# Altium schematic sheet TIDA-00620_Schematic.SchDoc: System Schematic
size 431 x 279 mm; Date: Not shown in title block; ApprovedBy: Not shown in title block; CheckedBy: Not shown in title block; Author: Not shown in title block; CompanyName: Not shown in title block; DrawnBy: Koh Hamasaki; Engineer: Not shown in title block; Organization: Not shown in title block; Address1: Not shown in title block; Address2: Not shown in title block; Address3: Not shown in title block; Address4: Not shown in title block; DocumentNumber: 1; Revision: Use project parameter SCH_Rev; SheetNumber: 1; SheetTotal: 2; PageSetup: Record=PageOptions¦CenterHorizontal=True¦CenterVertical=True¦PrintScale=0.64¦XCorrection=1.00¦YCorrection=1.00¦PrintKind=0¦BorderSize=5000000¦LeftOffset=0¦BottomOffset=0¦Orientation=2¦PaperLength=1000¦PaperWidth=1000¦Scale=100¦PaperSource=15¦PrintQuality=600¦MediaType=1¦DitherType=10¦PrintScaleMode=1¦PaperKind=Letter
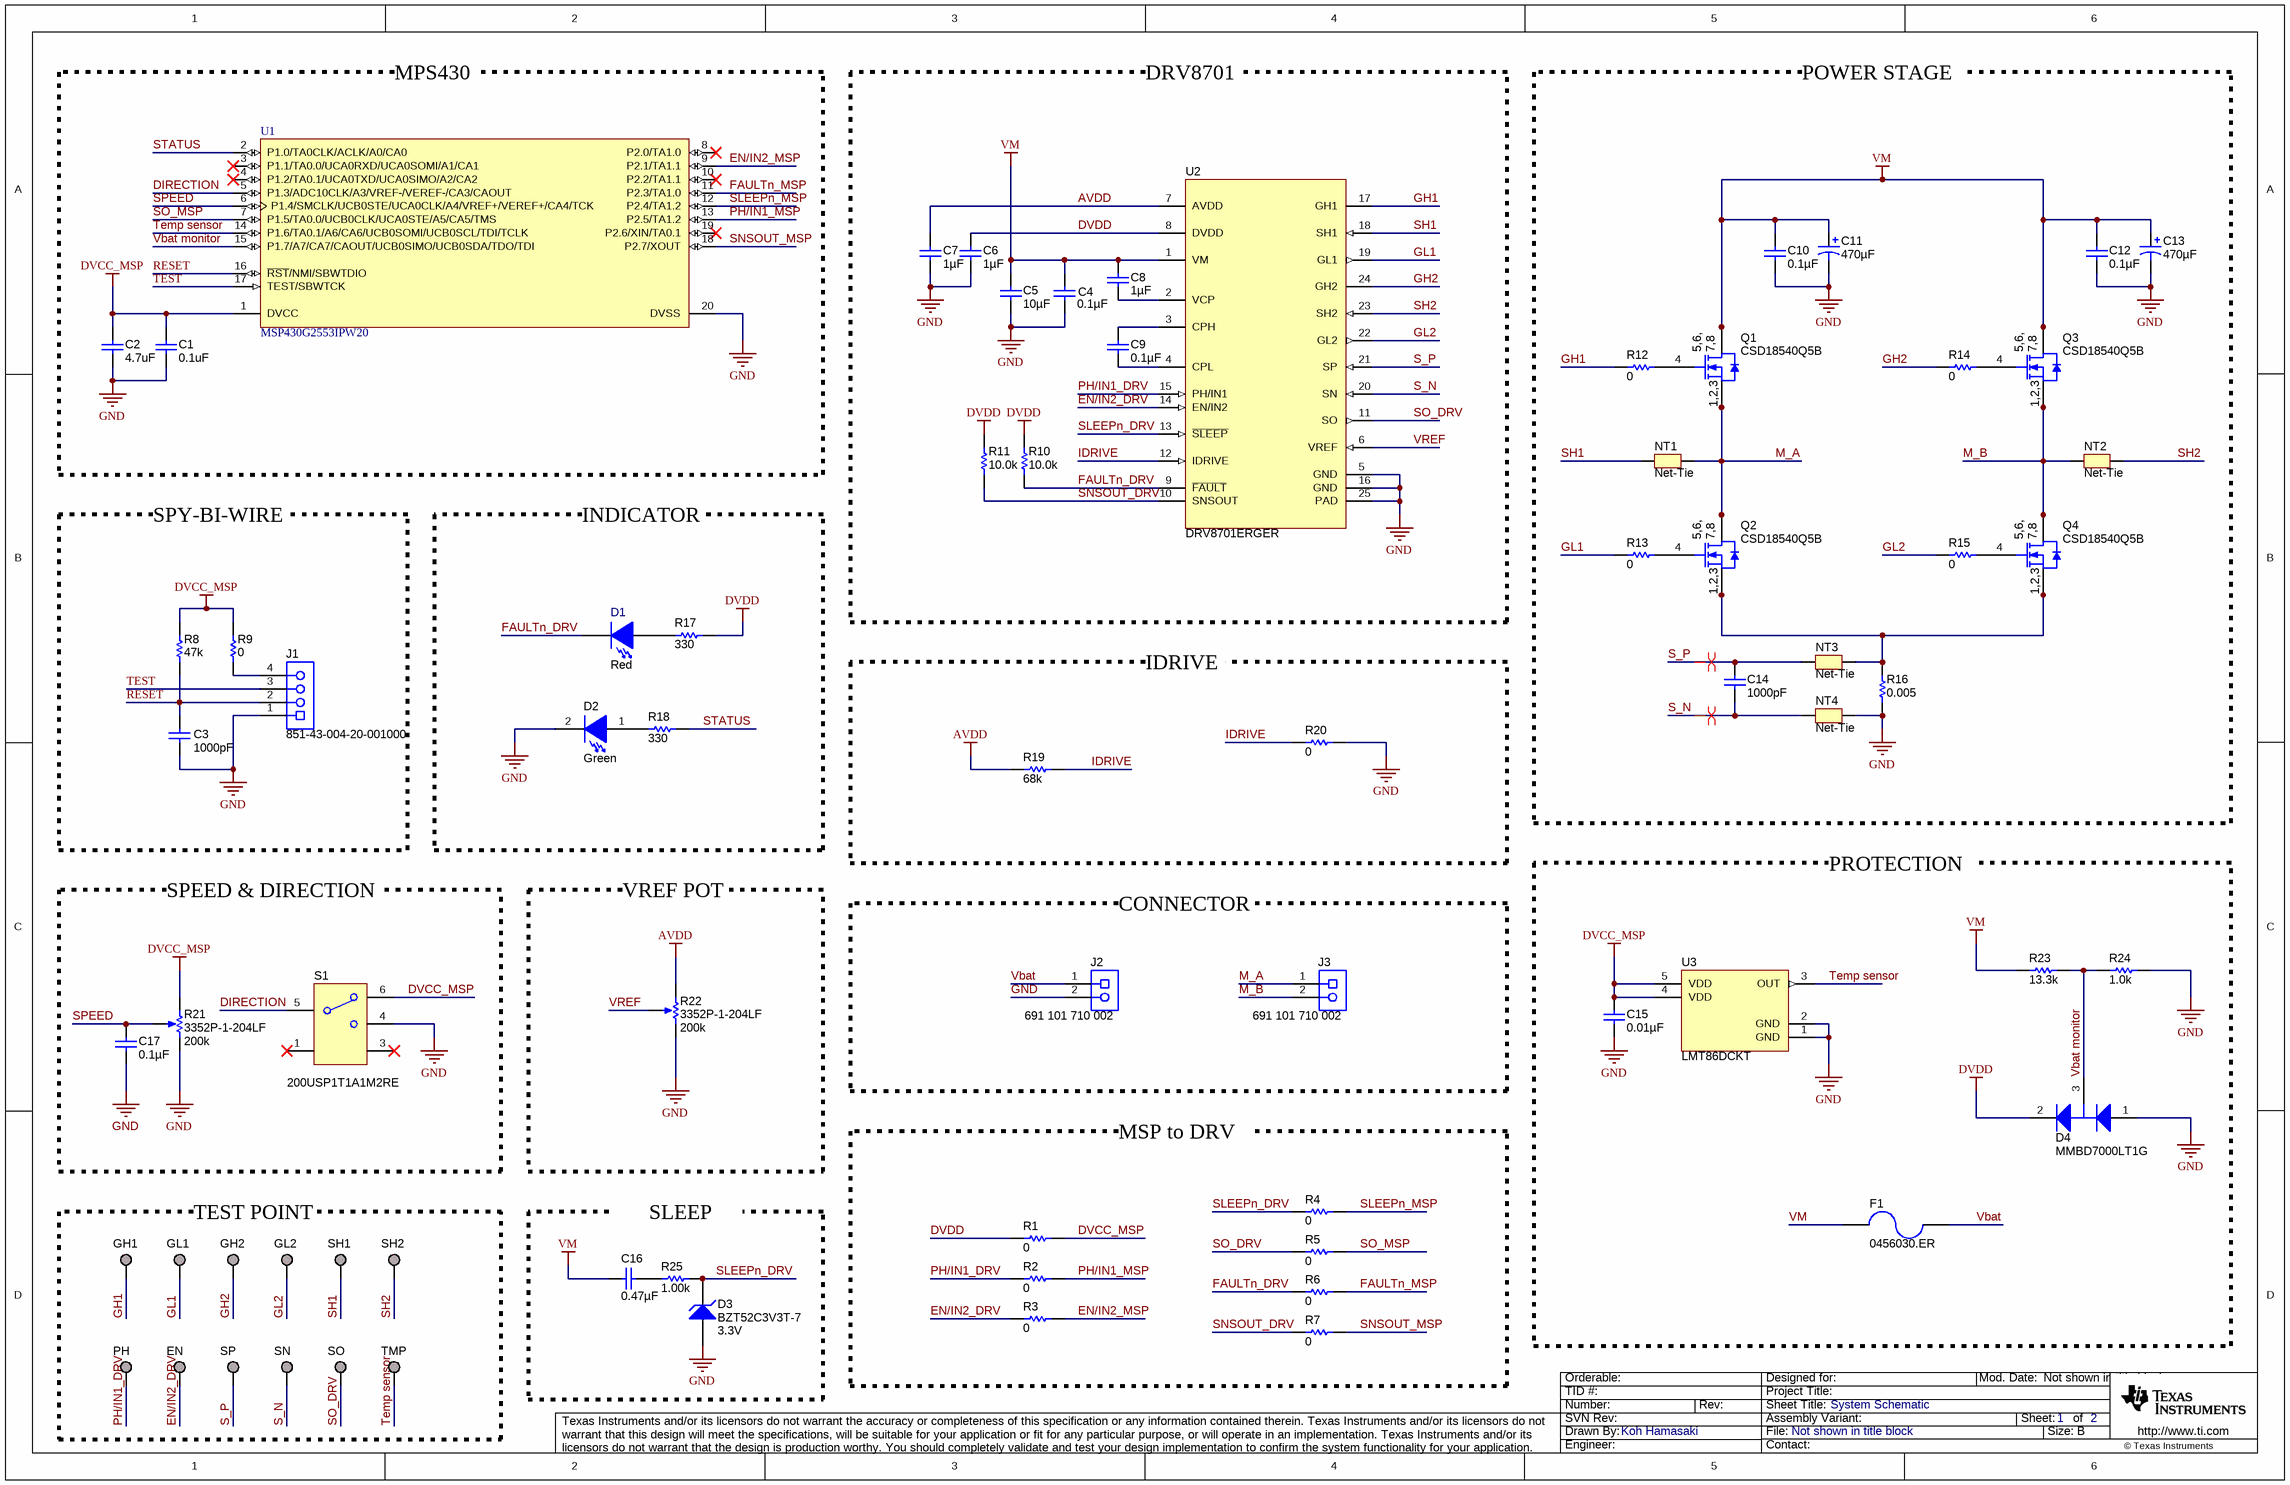
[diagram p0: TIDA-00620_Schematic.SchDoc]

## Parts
C1  ValueDisplayed: 0.1uF  [0603L]  (hidden comment: C0603C104K8RACTU)
C2  ValueDisplayed: 4.7uF  [0805L]  (hidden comment: C2012X7R1A475M)
C3  ValueDisplayed: 1000pF  [0603L]  (hidden comment: GRM188R71C102KA01D)
C4  ValueDisplayed: 0.1µF  [1206L]  (hidden comment: GRM319R71H104KA01D)
C5  ValueDisplayed: 10µF  [1210L]  (hidden comment: GRM32ER71H106KA12L)
C6  ValueDisplayed: 1µF  [0603L]  (hidden comment: GRM188R60J105KA01D)
C7  ValueDisplayed: 1µF  [0603L]  (hidden comment: GRM188R60J105KA01D)
C8  ValueDisplayed: 1µF  [1206L]  (hidden comment: GRM319R71C105KAA3D)
C9  ValueDisplayed: 0.1µF  [0402L]  (hidden comment: GRM155R71C104KA88D)
C10  ValueDisplayed: 0.1µF  [1206L]  (hidden comment: GRM319R71H104KA01D)
C11  ValueDisplayed: 470µF  [CAPPRD350W60D800H2000]  (hidden comment: EEU-FR1V471LB)
C12  ValueDisplayed: 0.1µF  [1206L]  (hidden comment: GRM319R71H104KA01D)
C13  ValueDisplayed: 470µF  [CAPPRD350W60D800H2000]  (hidden comment: EEU-FR1V471LB)
C14  ValueDisplayed: 1000pF  [0402L]  (hidden comment: GRM155R71C102KA01D)
C15  ValueDisplayed: 0.01µF  [0603L]  (hidden comment: GRM188R70J103KA01D)
C16  ValueDisplayed: 0.47µF  [0402L]  (hidden comment: GRM155R61A474KE15D)
C17  ValueDisplayed: 0.1µF  [0402]  (hidden comment: GCM155R71C104KA55D)
D1  value Red  [LED_LTST-C170]  (hidden comment: nFAULT)
D2  value Green  [LED_LTST-C171]  (hidden comment: LTST-C171GKT)
D3  BZT52C3V3T-7  value 3.3V  [SOD-523]
D4  MMBD7000LT1G  [SOT-23]
EN  TESTPOINT  [TP_25MIL-SMT]  (value not drawn)  (no BOM)
F1  0456030.ER  [FUSE_0456030]
GH1  TESTPOINT  [TP_25MIL-SMT]  (value not drawn)  (no BOM)
GH2  TESTPOINT  [TP_25MIL-SMT]  (value not drawn)  (no BOM)
GL1  TESTPOINT  [TP_25MIL-SMT]  (value not drawn)  (no BOM)
GL2  TESTPOINT  [TP_25MIL-SMT]  (value not drawn)  (no BOM)
J1  851-43-004-20-001000  [CONN_851-43-004-20-001000]
J2  691 101 710 002  [Wurth_691101710002]
J3  691 101 710 002  [Wurth_691101710002]
NT1  Net-Tie  [Net-Tie_10milWide_30milLong]  (net tie, no BOM)
NT2  Net-Tie  [Net-Tie_10milWide_30milLong]  (net tie, no BOM)
NT3  Net-Tie  [Net-Tie_10milWide_30milLong]  (net tie, no BOM)
NT4  Net-Tie  [Net-Tie_10milWide_30milLong]  (net tie, no BOM)
PH  TESTPOINT  [TP_25MIL-SMT]  (value not drawn)  (no BOM)
Q1  CSD18540Q5B  [TRANS_NexFET_Q5B]
Q2  CSD18540Q5B  [TRANS_NexFET_Q5B]
Q3  CSD18540Q5B  [TRANS_NexFET_Q5B]
Q4  CSD18540Q5B  [TRANS_NexFET_Q5B]
R1  ValueDisplayed: 0  [0402L]  (hidden comment: CRCW04020000Z0ED)
R2  ValueDisplayed: 0  [0402L]  (hidden comment: CRCW04020000Z0ED)
R3  ValueDisplayed: 0  [0402L]  (hidden comment: CRCW04020000Z0ED)
R4  ValueDisplayed: 0  [0402L]  (hidden comment: CRCW04020000Z0ED)
R5  ValueDisplayed: 0  [0402L]  (hidden comment: CRCW04020000Z0ED)
R6  ValueDisplayed: 0  [0402L]  (hidden comment: CRCW04020000Z0ED)
R7  ValueDisplayed: 0  [0402L]  (hidden comment: CRCW04020000Z0ED)
R8  value 47k  [0603L]  (hidden comment: CRCW060347K0JNEA)
R9  value 0  [0603L]  (hidden comment: CRCW06030000Z0EA)
R10  ValueDisplayed: 10.0k  [0402L]  (hidden comment: ERJ-2RKF1002X)
R11  ValueDisplayed: 10.0k  [0402L]  (hidden comment: ERJ-2RKF1002X)
R12  ValueDisplayed: 0  [0402L]  (hidden comment: CRCW04020000Z0ED)
R13  ValueDisplayed: 0  [0402L]  (hidden comment: CRCW04020000Z0ED)
R14  ValueDisplayed: 0  [0402L]  (hidden comment: CRCW04020000Z0ED)
R15  ValueDisplayed: 0  [0402L]  (hidden comment: CRCW04020000Z0ED)
R16  ValueDisplayed: 0.005  [4320]  (hidden comment: KRL11050-C-R005-F-T1)
R17  ValueDisplayed: 330  [0603L]  (hidden comment: RC0603FR-07330RL)
R18  ValueDisplayed: 330  [0603L]  (hidden comment: RC0603FR-07330RL)
R19  ValueDisplayed: 68k  [0402]  (hidden comment: CRCW040268K0JNED)
R20  ValueDisplayed: 0  [0402L]  (hidden comment: CRCW04020000Z0ED)
R21  3352P-1-204LF  value 200k  [Bourns_3352P]
R22  3352P-1-204LF  value 200k  [Bourns_3352P]
R23  ValueDisplayed: 13.3k  [0402L]  (hidden comment: CRCW040213K3FKED)
R24  ValueDisplayed: 1.0k  [0402L]  (hidden comment: CRCW04021K00JNED)
R25  ValueDisplayed: 1.00k  [0402L]  (hidden comment: CRCW04021K00FKED)
S1  200USP1T1A1M2RE  [SW_200USP1T1A1M2]
SH1  TESTPOINT  [TP_25MIL-SMT]  (value not drawn)  (no BOM)
SH2  TESTPOINT  [TP_25MIL-SMT]  (value not drawn)  (no BOM)
SN  TESTPOINT  [TP_25MIL-SMT]  (value not drawn)  (no BOM)
SO  TESTPOINT  [TP_25MIL-SMT]  (value not drawn)  (no BOM)
SP  TESTPOINT  [TP_25MIL-SMT]  (value not drawn)  (no BOM)
TMP  TESTPOINT  [TP_25MIL-SMT]  (value not drawn)  (no BOM)
U1  MSP430G2553IPW20  [PW0020A_N]
U2  DRV8701ERGER  [RGE0024F]
U3  LMT86DCKT  [DCK0005A_N]

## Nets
AVDD: C7.1 R19.1 R22.1(CCW) U2.7(AVDD)
DVCC_MSP: C1.1 C2.1 C15.1 R1.2 R8.2 R9.2 R21.1(CCW) S1.6 U1.1(DVCC) U3.4(VDD) U3.5(VDD)
DVDD: C6.1 D4.2(K) R1.1 R10.2 R11.2 R17.2 U2.8(DVDD)
GND: C1.2 C2.2 C3.2 C4.2 C5.2 C6.2 C7.2 C10.2 C11.2(-) C12.2 C13.2(-) C15.2 C17.2 D2.2(K) D3.2(A) D4.1(A) J1.1 J2.2 NT4.2 R16.1 R20.2 R21.3(CW) R22.3(CW) R24.2 S1.4 U1.20(DVSS) U2.5(GND) U2.16(GND) U2.25(PAD) U3.1(GND) U3.2(GND)
VM: C4.1 C5.1 C8.1 C10.1 C11.1(+) C12.1 C13.1(+) C16.2 F1.2 Q1.5(D) Q1.6(D) Q1.7(D) Q1.8(D) Q3.5(D) Q3.6(D) Q3.7(D) Q3.8(D) R23.1 U2.1(VM)
DIRECTION: S1.5(COM) U1.5(P1.3/ADC10CLK/A3/VREF-/VEREF-/CA3/CAOUT)
EN/IN2_DRV: EN.1 R3.1 U2.14(EN/IN2)
EN/IN2_MSP: R3.2 U1.9(P2.1/TA1.1)
FAULTn_DRV: D1.2(K) R6.1 R10.1 U2.9(~{FAULT})
FAULTn_MSP: R6.2 U1.11(P2.3/TA1.0)
GH1: GH1.1 R12.1 U2.17(GH1)
GH2: GH2.1 R14.1 U2.24(GH2)
GL1: GL1.1 R13.1 U2.19(GL1)
GL2: GL2.1 R15.1 U2.22(GL2)
IDRIVE: R19.2 R20.1 U2.12(IDRIVE)
M_A: J3.1 NT1.2 Q1.1(S) Q1.2(S) Q1.3(S) Q2.5(D) Q2.6(D) Q2.7(D) Q2.8(D)
M_B: J3.2 NT2.1 Q3.1(S) Q3.2(S) Q3.3(S) Q4.5(D) Q4.6(D) Q4.7(D) Q4.8(D)
PH/IN1_DRV: PH.1 R2.1 U2.15(PH/IN1)
PH/IN1_MSP: R2.2 U1.13(P2.5/TA1.2)
RESET: C3.1 J1.2 R8.1 U1.16(~{RST}/NMI/SBWTDIO)
S_N: C14.2 NT4.1 SN.1 U2.20(SN)
S_P: C14.1 NT3.1 SP.1 U2.21(SP)
SH1: NT1.1 SH1.1 U2.18(SH1)
SH2: NT2.2 SH2.1 U2.23(SH2)
SLEEPn_DRV: D3.1(K) R4.1 R25.2 U2.13(~{SLEEP})
SLEEPn_MSP: R4.2 U1.12(P2.4/TA1.2)
SNSOUT_DRV: R7.1 R11.1 U2.10(SNSOUT)
SNSOUT_MSP: R7.2 U1.18(P2.7/XOUT)
SO_DRV: R5.1 SO.1 U2.11(SO)
SO_MSP: R5.2 U1.7(P1.5/TA0.0/UCB0CLK/UCA0STE/A5/CA5/TMS)
SPEED: C17.1 R21.2(WIPER) U1.6(P1.4/SMCLK/UCB0STE/UCA0CLK/A4/VREF+/VEREF+/CA4/TCK)
STATUS: R18.2 U1.2(P1.0/TA0CLK/ACLK/A0/CA0)
Temp sensor: TMP.1 U1.14(P1.6/TA0.1/A6/CA6/UCB0SOMI/UCB0SCL/TDI/TCLK) U3.3(OUT)
TEST: J1.3 U1.17(TEST/SBWTCK)
Vbat: F1.1 J2.1
Vbat monitor: D4.3(C) R23.2 R24.1 U1.15(P1.7/A7/CA7/CAOUT/UCB0SIMO/UCB0SDA/TDO/TDI)
VREF: R22.2(WIPER) U2.6(VREF)
NetC8_2: C8.2 U2.2(VCP)
NetC9_1: C9.1 U2.3(CPH)
NetC9_2: C9.2 U2.4(CPL)
NetC16_1: C16.1 R25.1
NetD1_1: D1.1(A) R17.1
NetD2_1: D2.1(A) R18.1
NetJ1_4: J1.4 R9.1
NetNT3_2: NT3.2 Q2.1(S) Q2.2(S) Q2.3(S) Q4.1(S) Q4.2(S) Q4.3(S) R16.2
NetQ1_4: Q1.4(G) R12.2
NetQ2_4: Q2.4(G) R13.2
NetQ3_4: Q3.4(G) R14.2
NetQ4_4: Q4.4(G) R15.2

Not connected (* = marked no-connect by the designer): S1 1* 3*; U1 3(P1.1/TA0.0/UCA0RXD/UCA0SOMI/A1/CA1)* 4(P1.2/TA0.1/UCA0TXD/UCA0SIMO/A2/CA2)* 8(P2.0/TA1.0)* 10(P2.2/TA1.1)* 19(P2.6/XIN/TA0.1)*

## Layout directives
differential pair: S_N, S_P

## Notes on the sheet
- MPS430
- DRV8701
- POWER STAGE
- SPY-BI-WIRE
- INDICATOR
- IDRIVE
- SPEED & DIRECTION
- VREF POT
- PROTECTION
- CONNECTOR
- MSP to DRV
- TEST POINT
- SLEEP

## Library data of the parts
C1 = C0603C104K8RACTU: CAP, CERM, 0.1uF, 10V, +/-10%, X7R, 0603; Manufacturer: Kemet; Polarized: N; CompType: Capacitor; U/M: EA; Cap_F: 0.0000001; Tolerance_%: 10; Value1: Unknown; TaMin_C: -55; TaMax_C: 125; Cap_Case: 0603
C2 = C2012X7R1A475M: CAP, CERM, 4.7uF, 10V, +/-20%, X7R, 0805; Manufacturer: TDK; Polarized: N; CompType: Capacitor; U/M: EA; Cap_F: 0.0000047; Tolerance_%: 20; Value1: Unknown; VDC_V: 10; TaMin_C: -55; TaMax_C: 125; Cap_Case: 0805
C3 = GRM188R71C102KA01D: CAP, CERM, 1000pF, 16V, +/-10%, X7R, 0603; Manufacturer: MuRata; Polarized: N; CompType: Capacitor; U/M: EA; Cap_F: 0.000000001; Tolerance_%: 10; Value1: Unknown; VDC_V: 16; TaMin_C: -55; TaMax_C: 125; Cap_Case: 0603
C4 C10 C12 = GRM319R71H104KA01D: CAP, CERM, 0.1 µF, 50 V, +/- 10%, X7R, 1206; Manufacturer: MuRata; Polarized: N; CompType: Capacitor; Value: 0.1uF; U/M: EA; Cap_F: 0.0000001; Tolerance_%: 10; ESR_ohm: 0.01; Value1: 0.01 ohm; VDC_V: 50; Value2: 50V; IRMS_A: 0.9; TaMin_C: -55; TaMax_C: 125; Cap_Case: 1206
C5 = GRM32ER71H106KA12L: CAP, CERM, 10 µF, 50 V, +/- 10%, X7R, 1210; Manufacturer: MuRata; Polarized: N; CompType: Capacitor; Value: 10uF; U/M: EA; Cap_F: 0.00001; Tolerance_%: 10; Value1: Unknown; VDC_V: 50; Value2: 50V; TaMin_C: -55; TaMax_C: 125; Cap_Case: 1210
C6 C7 = GRM188R60J105KA01D: CAP, CERM, 1 µF, 6.3 V, +/- 10%, X5R, 0603; Manufacturer: MuRata; Polarized: N; CompType: Capacitor; Value: 1uF; U/M: EA; Cap_F: 0.000001; Tolerance_%: 10; Value1: Unknown; VDC_V: 6.3; Value2: 6.3V; TaMin_C: -55; TaMax_C: 85; Cap_Case: 0603
C8 = GRM319R71C105KAA3D: CAP, CERM, 1 µF, 16 V, +/- 10%, X7R, 1206; Manufacturer: MuRata; Polarized: N; CompType: Capacitor; Value: 1uF; U/M: EA; Cap_F: 0.000001; Tolerance_%: 10; Value1: Unknown; VDC_V: 16; Value2: 16V; TaMin_C: -55; TaMax_C: 125; Cap_Case: 1206
C9 = GRM155R71C104KA88D: CAP, CERM, 0.1 µF, 16 V, +/- 10%, X7R, 0402; Manufacturer: MuRata; Polarized: N; CompType: Capacitor; Value: 0.1uF; U/M: EA; Cap_F: 0.0000001; Tolerance_%: 10; Value1: Unknown; VDC_V: 16; Value2: 16V; TaMin_C: -55; TaMax_C: 125; Cap_Case: 0402
C11 C13 = EEU-FR1V471LB: CAP, AL, 470 µF, 35 V, +/- 20%, 0.03 ohm, TH; Manufacturer: Panasonic; Polarized: Y; CompType: Capacitor; Value: 470uF; U/M: EA; Cap_F: 0.00047; Tolerance_%: 20; VDC_V: 35; Value2: 35V; ESR_ohm: 0.03; IRMS_A: 1.56; TaMin_C: -40; TaMax_C: 105; Cap_Case: CAPR_8x20mm
C14 = GRM155R71C102KA01D: CAP, CERM, 1000pF, 16V, +/-10%, X7R, 0402; Manufacturer: MuRata; Polarized: N; CompType: Capacitor; U/M: EA; Cap_F: 0.000000001; Tolerance_%: 10; Value1: Unknown; VDC_V: 16; TaMin_C: -55; TaMax_C: 125; Cap_Case: 0402
C15 = GRM188R70J103KA01D: CAP, CERM, 0.01 µF, 6.3 V, +/- 10%, X7R, 0603; Manufacturer: MuRata; Polarized: N; CompType: Capacitor; Value: 0.01uF; U/M: EA; Cap_F: 0.00000001; Tolerance_%: 10; Value1: Unknown; VDC_V: 6.3; Value2: 6.3V; TaMin_C: -55; TaMax_C: 125; Cap_Case: 0603
C16 = GRM155R61A474KE15D: CAP, CERM, 0.47 µF, 10 V, +/- 10%, X5R, 0402; Manufacturer: MuRata; Polarized: N; CompType: Capacitor; Value: 0.47uF; U/M: EA; Cap_F: 0.00000047; Tolerance_%: 10; Value1: Unknown; Value2: 10V; TaMin_C: -55; TaMax_C: 85; Cap_Case: 0402
C17 = GCM155R71C104KA55D: CAP, CERM, 0.1 µF, 16 V, +/- 10%, X7R, 0402; Manufacturer: MuRata; Polarized: N; CompType: Capacitor; Value: 0.1uF; U/M: EA; Cap_F: 0.0000001; Tolerance_%: 10; Value1: Unknown; VDC_V: 16; Value2: 16V; TaMin_C: -55; TaMax_C: 125; AEC Category: Q200
D1 = LTST-C170KRKT: LED, Red, SMD; Manufacturer: Lite-On; DK Part Number: 160-1415-1-ND; Type: AlInGaP; Vf_V: 2; Value2: 2V; Value1: W; U/M: EA
D2 = LTST-C171GKT: LED, Green, SMD; Manufacturer: Lite-On; Type: AlInGaP; Vf_V: 2.1; Value2: 2.1V; Io_A: 20; Value1: W; U/M: EA
D3 = BZT52C3V3T-7: Diode, Zener, 3.3 V, 300 mW, SOD-523; Manufacturer: Diodes Inc.; SymbolCreator: a0412235; U/M: EA; Power_W: 0.3; Vz_V: 3.3; Value1: 0.3W; RJA_CperW: 417
D4 = MMBD7000LT1G: Diode, Switching, 100 V, 0.2 A, SOT-23; Manufacturer: ON Semiconductor; U/M: EA; Value: 100V; Value1: 0.2A; Io_A: 0.2; Vr_V: 100; TJmax_C: 150
EN GH1 GH2 GL1 GL2 PH SH1 SH2 SN SO SP TMP = TESTPOINT: TEST POINT.  No entry in BOM.
F1 = 0456030.ER: Fuse, 30 A, 72 V, SMD; Manufacturer: Littelfuse; U/M: EA; VDC_V: 72; VAC_V: 125; Irating_A: 30; Rtyp_Ohm: 0.00132; MeltingTyp: 81; Vdrop: 0.0699
J1 = 851-43-004-20-001000: SOCKET .050" GRID SIP 4 POS R/A, TH; Manufacturer: Mill-Max; SymbolCreator: a0411947; CompType: Header; U/M: EA
J2 J3 = 691 101 710 002: Terminal Block, 5 mm, 2x1, Tin, TH; Manufacturer: Wurth Elektronik; SymbolCreator: a0412235; U/M: EA
NT1-NT4 = Net-Tie: Single point connection between nets.; SymbolCreator: codlsc
Q1-Q4 = CSD18540Q5B: MOSFET, N-CH, 60 V, 28 A, SON 5x6mm; Manufacturer: Texas Instruments; Alternate Manufacturer: None; U/M: EA; ChType: N; Value: 60V; VdsMax_V: 60; Value1: 0.0033 ohm; Rdson45_ohm: 0.0033; Value2: 41 nC; QgTyp_nC: 41; Vgs_V: 20; IdsMax_A: 28
R1-R7 R12-R15 R20 = CRCW04020000Z0ED: RES, 0, 5%, 0.063 W, 0402; Manufacturer: Vishay-Dale; CompType: Resistor; Value: 0; Value_Code: 0000; Tolerance_%: 5; Power_W: 0.063; Value2: 0.063W; VDC_V: 50; TempCo: 200 ppm/C; EIA_Code: E24; U/M: EA
R8 = CRCW060347K0JNEA: RES, 47k ohm, 5%, 0.1W, 0603; Manufacturer: Vishay-Dale; CompType: Resistor; Res_ohm: 47000; Value_Code: 47k0; Tolerance_%: 5; Power_W: 0.1; VDC_V: 75; TempCo: 200 ppm/C; EIA_Code: E24; U/M: EA
R9 = CRCW06030000Z0EA: RES, 0 ohm, 5%, 0.1W, 0603; Manufacturer: Vishay-Dale; CompType: Resistor; Value_Code: 0000; Tolerance_%: 5; Power_W: 0.1; VDC_V: 75; TempCo: 200 ppm/C; EIA_Code: E24; U/M: EA
R10 R11 = ERJ-2RKF1002X: RES, 10.0 k, 1%, 0.1 W, 0402; Manufacturer: Panasonic; CompType: Resistor; Value: 10.0k; Res_ohm: 10000; Value_Code: 10k0; Tolerance_%: 1; Power_W: 0.1; Value2: 0.1W; VDC_V: 50; TempCo: 100 ppm/C; EIA_Code: E96; U/M: EA
R16 = KRL11050-C-R005-F-T1: RES, 0.005, 1%, 6 W, 4320_WIDE; Manufacturer: Susumu Co Ltd; CompType: Resistor; Value: 0.005; Value_Code: 5L000; Tolerance_%: 1; Power_W: 6; Value2: 6W; TempCo: 50 ppm/C; EIA_Code: E96; U/M: EA
R17 R18 = RC0603FR-07330RL: RES, 330, 1%, 0.1 W, 0603; Manufacturer: Yageo America; CompType: Resistor; Value: 330; Value_Code: 330R; Tolerance_%: 1; Power_W: 0.1; Value2: 0.1W; VDC_V: 150; TempCo: 200 ppm/C; U/M: EA
R19 = CRCW040268K0JNED: RES, 68 k, 5%, 0.063 W, 0402; Manufacturer: Vishay-Dale; CompType: Resistor; Value: 68k; Res_ohm: 68000; Value_Code: 68k0; Tolerance_%: 5; Power_W: 0.063; Value2: 0.063W; VDC_V: 50; TempCo: 200 ppm/C; EIA_Code: E24; U/M: EA
R21 R22 = 3352P-1-204LF: Trimmer, 200 K, 0.5 W, TH; Manufacturer: Bourns; Sim Note: Enter the Resistance value and the set point into parameter fields.; SymbolCreator: a0412235
R23 = CRCW040213K3FKED: RES, 13.3 k, 1%, 0.063 W, 0402; Manufacturer: Vishay-Dale; CompType: Resistor; Value: 13.3k; Res_ohm: 13300; Value_Code: 13k3; Tolerance_%: 1; Power_W: 0.063; Value2: 0.063W; VDC_V: 50; TempCo: 100 ppm/C; EIA_Code: E96; U/M: EA
R24 = CRCW04021K00JNED: RES, 1.0 k, 5%, 0.063 W, 0402; Manufacturer: Vishay-Dale; CompType: Resistor; Value: 1.0k; Res_ohm: 1000; Value_Code: 1k00; Tolerance_%: 5; Power_W: 0.063; Value2: 0.063W; VDC_V: 50; TempCo: 200 ppm/C; EIA_Code: E24; U/M: EA
R25 = CRCW04021K00FKED: RES, 1.00 k, 1%, 0.063 W, 0402; Manufacturer: Vishay-Dale; CompType: Resistor; Value: 1.00k; Res_ohm: 1000; Value_Code: 1k00; Tolerance_%: 1; Power_W: 0.063; Value2: 0.063W; VDC_V: 50; TempCo: 100 ppm/C; EIA_Code: E96; U/M: EA
S1 = 200USP1T1A1M2RE: Switch, SPDT, On-On, 2 Pos, TH; Manufacturer: E-Switch; SymbolCreator: Altium; VDC_V: 20; PositionCount: 2; CurrentRating_mA: 400
U1 = MSP430G2553IPW20: 16 MHz Mixed Signal Microcontroller with 16 KB Flash, 512 B SRAM and 24 GPIOs, -40 to 85 degC, 20-pin SOP (PW), Green (RoHS & no Sb/Br); Alternate Manufacturer: Texas Instruments; Alternate PartNumber: Equivalent; ADC: 10-bit SAR; ADC Channels: 8; Brown Out Reset: Yes; Flash(KB): 16; GPIO: 24; Pin/Package: 0DIESALE, 0WAFERSALE, 20PDIP, 20TSSOP, 28TSSOP, 32QFN; SRAM(B): 512; SubFamily: Value Line; Timers - 16-bit: 2; USCI_A (UART/LIN/IrDA/SPI): 1
U2 = DRV8701ERGER: H-Bridge Gate Driver, RGE0024F; Alternate PartNumber: DRV8701ERGET; Manufacturer: Texas Instruments; SymbolCreator: Altium; CompType: IC; U/M: EA
U3 = LMT86DCKT: Analog Temperature Sensors with Class-AB Output, DCK0005A; Manufacturer: Texas Instruments; SymbolCreator: a0799628; CompType: IC; U/M: EA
